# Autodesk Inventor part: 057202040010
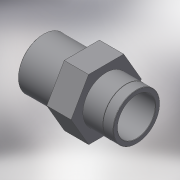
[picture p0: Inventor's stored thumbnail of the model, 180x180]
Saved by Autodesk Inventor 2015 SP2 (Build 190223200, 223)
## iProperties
Created: 2017-10
Part Number: 057202040010
Material: Generic
Description: PLASSON REDUCER THR-CEM REIN 40-(32)-1"
Document SubType Name: Modeling
Designer: KIM
Density: 1 g/cm^3
Appearance: Default
Author: KIM
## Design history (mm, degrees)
derived "057202.ipt"
feature "Solid1::057202.ipt"
tag "TaggingFeature1"
body "Solid1"
other parameters: "d0" = 63, "d1" = 32, "d2" = 47, "d3" = 30.291, "d4" = 28.8, "d8" = 36.8, "d13" = 0, "d14" = 0.32, "d16" = 16, "d17" = 26, "d18" = 24, "d19" = 0.1, "d20" = 6, "d21" = 36.8, "d_" = 32, "G_" = 30.291, "C_" = 47, "B_" = 16, "L_" = 26, "H_" = 63
